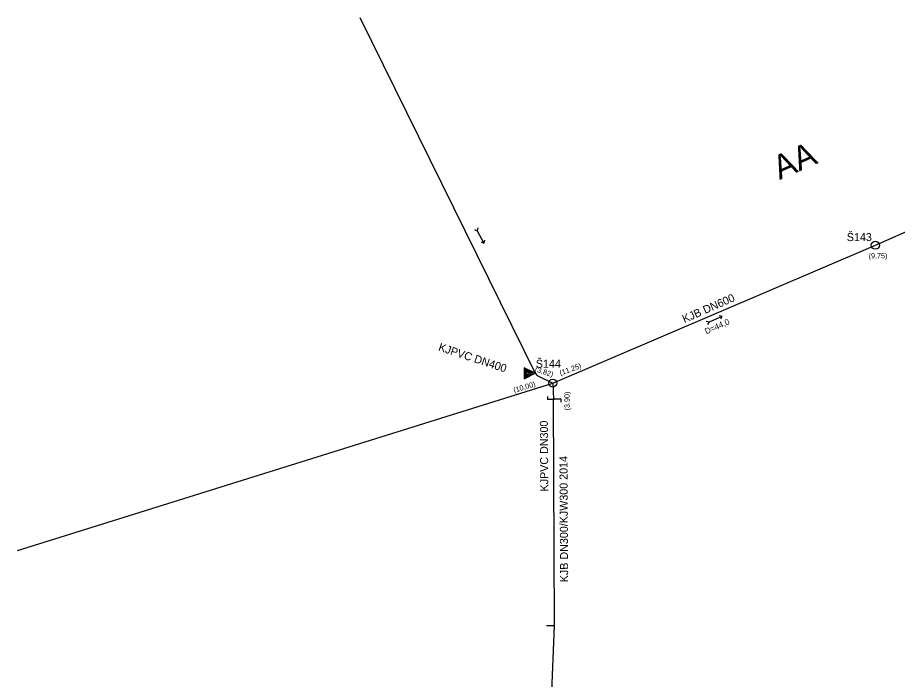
# Model space of a CAD drawing. Extents: x -539706 to -539225, y -1156458 to -1155912.
# Drawn here: x -539706.4 to -539596.4, y -1156127.6 to -1156044.9 of the extents above; entities that cross this region are included whole.
import ezdxf

# ---------------------------------------------------------------- set-up
doc = ezdxf.new("R2010")
doc.units = 0
for name, color, linetype in [('Vrstva 17', 7, 'Continuous'), ('Vrstva 29', 7, 'Continuous'), ('Vrstva 37', 7, 'Continuous'), ('Vrstva 38', 7, 'Continuous'), ('Vrstva 39', 7, 'Continuous'), ('Vrstva 54', 7, 'Continuous'), ('Vrstva 56', 7, 'Continuous'), ('Vrstva 57', 7, 'Continuous'), ('Vrstva 59', 7, 'Continuous'), ('Vrstva 60', 7, 'Continuous'), ('Vrstva 7', 7, 'Continuous'), ('Vrstva 8', 7, 'Continuous'), ('Vrstva 9', 7, 'Continuous')]:
    doc.layers.add(name, color=color, linetype=linetype)

msp = doc.modelspace()

# ---------------------------------------------------------------- linework, layer by layer
at = {"layer": 'Vrstva 17'}
msp.add_line((-539639.27, -1156120.87), (-539640.27, -1156120.87), dxfattribs=at)
at = {"layer": 'Vrstva 29'}
for centre in [(-539599.2, -1156073.37), (-539639.51, -1156090.58)]:
    msp.add_circle(centre, 0.5, dxfattribs=at)
at = {"layer": 'Vrstva 37'}
for p, q in [((-539643.079, -1156088.654), (-539643.08, -1156089.341)), ((-539641.7, -1156089.34), (-539643.079, -1156088.654)), ((-539643.08, -1156089.341), (-539643.079, -1156090.026)), ((-539643.079, -1156090.026), (-539641.7, -1156089.34))]:
    msp.add_line(p, q, dxfattribs=at)
for points in [[(-539642.981, -1156089.864), (-539641.925, -1156089.34), (-539642.98, -1156088.815), (-539642.981, -1156089.864)], [(-539642.877, -1156089.702), (-539642.149, -1156089.339), (-539642.878, -1156088.976), (-539642.877, -1156089.702)], [(-539642.78, -1156089.54), (-539642.376, -1156089.338), (-539642.781, -1156089.138), (-539642.78, -1156089.54)]]:
    msp.add_lwpolyline(points, dxfattribs=at)
at = {"layer": 'Vrstva 38'}
for points in [[(-539640.156, -1156092.256), (-539640.157, -1156092.6), (-539639.31, -1156092.599)], [(-539638.46, -1156092.942), (-539638.461, -1156092.6), (-539639.31, -1156092.599)]]:
    msp.add_lwpolyline(points, dxfattribs=at)
at = {"layer": 'Vrstva 39'}
for p, q in [((-539648.867, -1156071.18), (-539648.934, -1156071.567)), ((-539649.29, -1156071.4), (-539648.934, -1156071.567)), ((-539648.934, -1156071.567), (-539648.123, -1156073.123)), ((-539648.469, -1156072.957), (-539648.123, -1156073.123)), ((-539648.058, -1156072.742), (-539648.123, -1156073.123)), ((-539619.937, -1156082.936), (-539618.33, -1156082.235)), ((-539618.705, -1156082.144), (-539618.33, -1156082.235)), ((-539618.519, -1156082.569), (-539618.33, -1156082.235)), ((-539620.319, -1156082.843), (-539619.937, -1156082.936)), ((-539620.128, -1156083.281), (-539619.937, -1156082.936))]:
    msp.add_line(p, q, dxfattribs=at)
at = {"layer": 'Vrstva 8'}
for p, q in [((-539706.38, -1156111.5), (-539639.51, -1156090.58)), ((-539639.51, -1156090.58), (-539639.43, -1156092.61)), ((-539639.27, -1156120.87), (-539639.43, -1156092.61)), ((-539639.69, -1156130.54), (-539639.27, -1156120.87))]:
    msp.add_line(p, q, dxfattribs=at)
msp.add_lwpolyline([(-539641.7, -1156089.34), (-539641.45, -1156089.63), (-539639.51, -1156090.58)], dxfattribs=at)
at = {"layer": 'Vrstva 9'}
for p, q in [((-539663.6, -1156044.94), (-539641.7, -1156089.34)), ((-539599.2, -1156073.37), (-539553.23, -1156053.1)), ((-539639.51, -1156090.58), (-539599.2, -1156073.37))]:
    msp.add_line(p, q, dxfattribs=at)

# ---------------------------------------------------------------- texts
at = {"layer": 'Vrstva 54'}
msp.add_text('D=44,0 ', height=0.75, rotation=23.63236, dxfattribs=at).set_placement((-539620.318, -1156084.5))
at = {"layer": 'Vrstva 56'}
msp.add_text('(11.25)', height=0.65, rotation=20.23102, dxfattribs=at).set_placement((-539638.536, -1156089.649))
at = {"layer": 'Vrstva 57'}
for s, p in [('Š143', (-539602.76, -1156072.847)), ('Š144', (-539641.62, -1156088.665))]:
    msp.add_text(s, height=1, dxfattribs=at).set_placement(p)
at = {"layer": 'Vrstva 59'}
msp.add_text('(9,75)', height=0.65, dxfattribs=at).set_placement((-539600.041, -1156075))
for s, rotation, p in [('(3.82)', 341.74242, (-539641.796, -1156089.11)), ('(10,00)', 16.69972, (-539644.326, -1156091.792)), ('(3.90)', 90.32436, (-539637.396, -1156093.989))]:
    msp.add_text(s, height=0.65, rotation=rotation, dxfattribs=at).set_placement(p)
at = {"layer": 'Vrstva 60'}
msp.add_text('AA', height=3, rotation=23.63236, dxfattribs=at).set_placement((-539611.169, -1156065.234))
at = {"layer": 'Vrstva 7'}
for s, rotation, p in [('KJB DN600', 23.6347, (-539623.061, -1156083.09)), ('KJPVC DN400', 341.74242, (-539653.869, -1156086.493)), ('KJPVC DN300', 90.32436, (-539640.068, -1156104.106)), ('KJB DN300/KJW300 2014', 90.32436, (-539637.584, -1156115.44))]:
    msp.add_text(s, height=1, rotation=rotation, dxfattribs=at).set_placement(p)

doc.saveas('drawing.dxf')
